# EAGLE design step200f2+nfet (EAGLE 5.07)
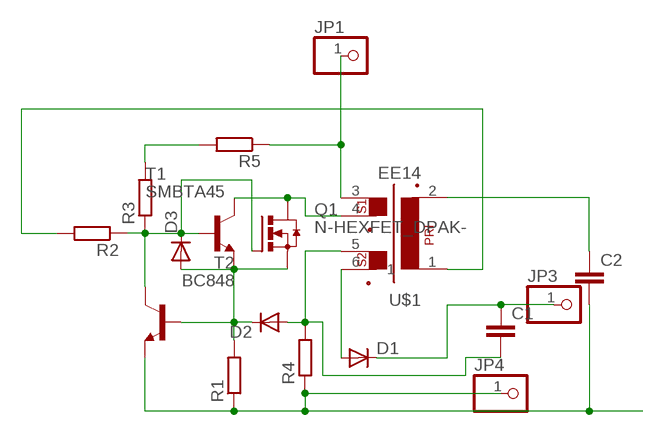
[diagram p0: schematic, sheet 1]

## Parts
C1  C-EU025-025X050  [C025-025X050]
C2  C-EUC0805  [C0805]
D1  DIODE-SMA-DO214  [SMA-DO214AC]
D2  DIODE-MINIMELF  [MINIMELF]
D3  DIODE-MINIMELF  [MINIMELF]
JP1  PINHD-1X11MM6  [1X1MM8]
JP3  PINHD-1X11MM6  [1X1MM8]
JP4  PINHD-1X11MM6  [1X1MM8]
Q1  N-HEXFET_DPAK-  [TO252]
R1  R-EU_R0805  [R0805]
R2  R-EU_R0805  [R0805]
R3  R-EU_R1206  [R1206]
R4  R-EU_R0805  [R0805]
R5  R-EU_R1206  [R1206]
T1  SMBTA45  BC848  [SOT23]
T2  BC848  [SOT23]
U$1  EE14  [EE14]

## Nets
A: D1.A U$1.6
B1C2: D3.C Q1.1(G) R2.1 R3.1 T1.B T2.C
C1: Q1.3(D) T1.C U$1.4
EB: D2.C D3.A Q1.2(S) R1.2 T1.E T2.B
N$1: R3.2 R5.2
N$4: R2.2 U$1.1
N$6: C2.1 U$1.2
NDOT: C1.2 D2.A R4.2 U$1.5
V+: JP1.1 R5.1 U$1.3
V-: C2.2 JP4.1 R1.1 R4.1 T2.E
VOUT+: C1.1 D1.K(C) JP3.1

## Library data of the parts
C1 C2 = rcl:C-EU: CAPACITOR, European symbol
D1-D3 = diode:DIODE-: DIODE
JP1 JP3 JP4 = pinhead:PINHD-1X1: PIN HEADER
Q1 = transistor-power:N-HEXFET_?-*: HEXFET® Power MOSFET
R1-R5 = rcl:R-EU_: RESISTOR, European symbol
T1 T2 = transistor:BC848: NPN TRANSISTOR
U$1 = trafo:EE14

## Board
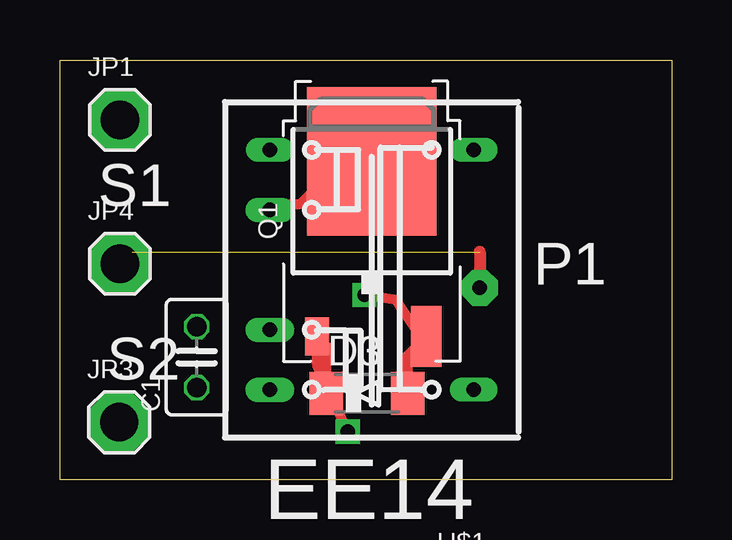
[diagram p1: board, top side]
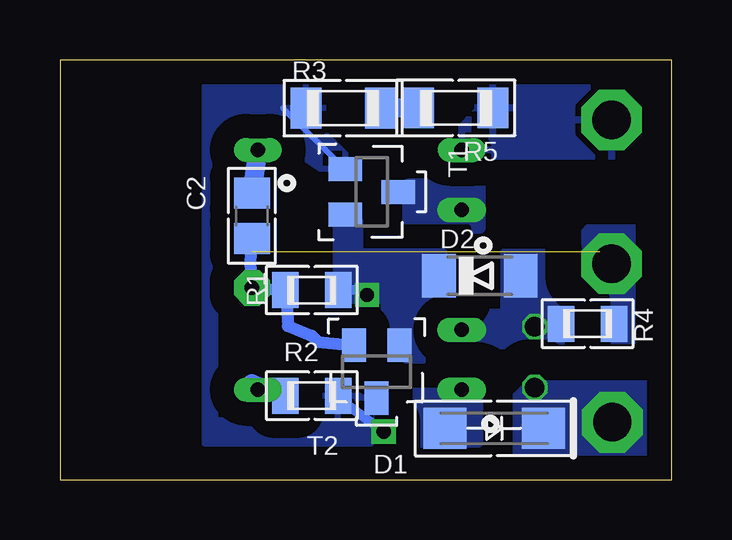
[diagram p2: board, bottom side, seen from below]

Size 25.5 x 17.5 mm. Coordinates in mm from the lower left corner, seen from the top.
Outline: 0,17.5 25.5,17.5 25.5,0 0,0 0,17.5
Copper layers (1*16): Top 0.035mm / dielectric 1.5mm / Bottom 0.035mm
Design rules "default *": minimum track width 10mil, minimum drill 20mil, track to track 8mil, track to pad 8mil, pad to pad 8mil, via to via 8mil, smd to smd 8mil, copper to edge 40mil, drill to drill 8mil, minimum pad ring 1mil, minimum via ring 8mil, stop-mask expansion 4mil, vias tented up to drill 0mil, thermal gap 10mil

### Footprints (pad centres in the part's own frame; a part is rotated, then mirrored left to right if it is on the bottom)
C025-025X050 = drill 0.813 octagon: 1 -1.27,0; 2 1.27,0
C0805 = smd 1.3 x 1.5: 1 -0.95,0; 2 0.95,0
SMA-DO214AC = smd 1.8 x 1.7: A 2.05,-0.127; K -2.05,-0.127
MINIMELF = smd 1.4 x 1.8: A 1.7,0; C -1.7,0
1X1MM8 = drill 1.6 pad 2.54 octagon: 1 0,0
TO252 = smd 1 x 1.6: 1 -2.28,-3.53 | smd 1.27 x 2.54: 2 2.28,-3.53 | smd 5.4 x 6.2: 3 0,3.77
R0805 = smd 1.1 x 1.5: 1 -1.1,0; 2 1.1,0
R1206 = smd 1.3 x 1.7: 1 -1.55,0; 2 1.55,0
SOT23 = smd 1 x 1.4: B -0.95,-1.1; C 0,1.1; E 0.95,-1.1
EE14 = drill 0.6 pad 1 long: 1 4.25,-5; 2 4.25,5; 3 -4.25,5 | drill 0.6 pad 1.016 long: 4 -4.25,2.5; 5 -4.25,-2.5; 6 -4.25,-5

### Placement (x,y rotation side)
C1  5.7,5.11 90 top
C2  17.5,11 270 bottom
D1  7.39,2.01 180 bottom
D2  8,8.5 0 bottom
D3  12.8,3.6 0 top
JP1  2.5,15 0 top
JP3  2.47,2.39 0 top
JP4  2.5,9 0 top
Q1  13,9.5 0 top
R1  15,7.9 0 bottom
R2  15,3.5 180 bottom
R3  13.69,15.49 0 bottom
R4  3.5,6.5 180 bottom
R5  9,15.5 180 bottom
T1  12.5,12 270 bottom
T2  12.3,4.5 180 bottom
U$1  13,8.75 0 top

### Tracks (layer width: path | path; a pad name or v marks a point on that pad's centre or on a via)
A
  pour Bottom (isolate 1, rank 3, no thermals): 8,4 10.5,4 11,3.5 11,1.5 8,1.5
B1C2  (via drill 0.6)
  Top 0.406: v12,2 10.72,4.78 Q1.1 11.1,5.59 D3.C
  Bottom 0.254: T1.B 16.19,15.5
  Bottom 0.406: v12,2 13.5,3.1 R2.1
  pour Bottom (isolate 1, rank 3): 14.5,16.5 19.5,16.5 19.5,1.5 12.5,1.5 12.5,4.5 14,4.5 15,5.5 15.5,7 18.5,7.5 18.5,2.5 19,2.5 19,14.5 17,14.5 14,12.5 13,13 14.5,14.5
C1
  Top 0.406: Q1.3 11.77,13.27 10,11.5 9,11.5 U$1.4
  pour Bottom (isolate 1, rank 3, no thermals): 8,12.3 11,12.3 11,10.5 8,10.5
EB  (via drill 0.6)
  Top 0.406: v12.7,7.7 14,7.5 15.03,5.97 Q1.2 14.5,5.19 D3.A
  Bottom 0.406: v12.7,7.7 12.5,7.9 R1.2
  pour Bottom (isolate 1, no thermals): 9.5,5 9.5,9.5 13,9.5 13,11 14,11 14,7.5 12,7.5 12,5
N$1
  Bottom 0.8: R5.2 R3.2
N$4
  Bottom 0.8: R2.2 17.5,4 U$1.1
N$6
  Bottom 0.8: C2.1 U$1.2
NDOT
  pour Bottom (isolate 1.5, rank 3, no thermals): 4,7 4,6 4.5,5.5 9,5.5 9.5,6 9.5,6.5 9,7 7,7 7,9.5 5,9.5 5,8
V+
  pour Bottom (isolate 1, rank 4): 3,16.5 6,16.5 8.1,16.4 8.1,15.4 9,14.5 9.5,13.5 2,13.5
V-  (via drill 0.6 pad 1.5)  (1 unrouted)
  Top 0.5: 17.5,9.5 v17.5,8 | JP4.1 3,9.5
  Bottom 0.254: C2.2 17.93,10
  Bottom 0.5: C2.2 17.55,9.05 v17.5,8 R1.1 16,6.4 15,6 14.75,5.75 T2.E
  pour Bottom (isolate 1.5, rank 4, no thermals): 1,10.5 3.5,10.5 4,10 4,8.5 3,7.5 3,5 1,5 1,9.5
VOUT+
  pour Bottom (isolate 1, rank 3, no thermals): 1.5,4 6,4 6.5,3.5 6.5,0.5 1,0.5 1,4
